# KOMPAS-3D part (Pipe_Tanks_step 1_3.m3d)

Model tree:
1. X Axis
2. Y Axis
3. Z Axis  (labels: T-Bend Dn 50; Pipe Dn 50; C:\Program Files\ASCON\KOMPAS-3D V10\Sys\graphic.lyt; Pipe_Tanks_step 1_3.m3d)
     Òîëùèíà ñòåíêè 1 = 1

Referenced files in C:\Documents and Settings\kashirsky\Мои документы\Camtasia Studio\Pipelines3D\Tanks\: Tanks_step 1.a3d, Tanks_step 1.spw
Referenced files in C:\Documents and Settings\kashirsky\Мои документы\Camtasia Studio\Pipelines3D\Tanks\Tanks_step 1_Pipes\: Pipe_Tanks_step 1_3.m3d
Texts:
  Pipe Dn 50
  Steel ASTM A295
  Three Point Plane
  Plane at Angle
  Line and Point Plane
  Axis through Two Vertices
  Axis of Feature
  Axis of Conical Surface
  Axis through Edge
  Trim by Surface
  Trim by Sketch
  Feature with No History
  Intersection Axis of Two Planes
  Two Line Plane
  Line and Face Plane
  Bend by line
  Hole in sheet body
  Cut in sheet body
  Point in CM
  Linear Dimension from Line to Point
  Surface Finish Symbol
  Geometric Tolerance Symbol
  Leader #1
  Leader #2
  Leader #3
  Shape Deviations and Datum
  Node point number
  Mark of coordination axis
  Node point designation
  Mark/Reference designation with leader
  Mark/reference designation on line
  Mark/Reference designation without leader
  T-Bend Dn 50
  Plane of section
